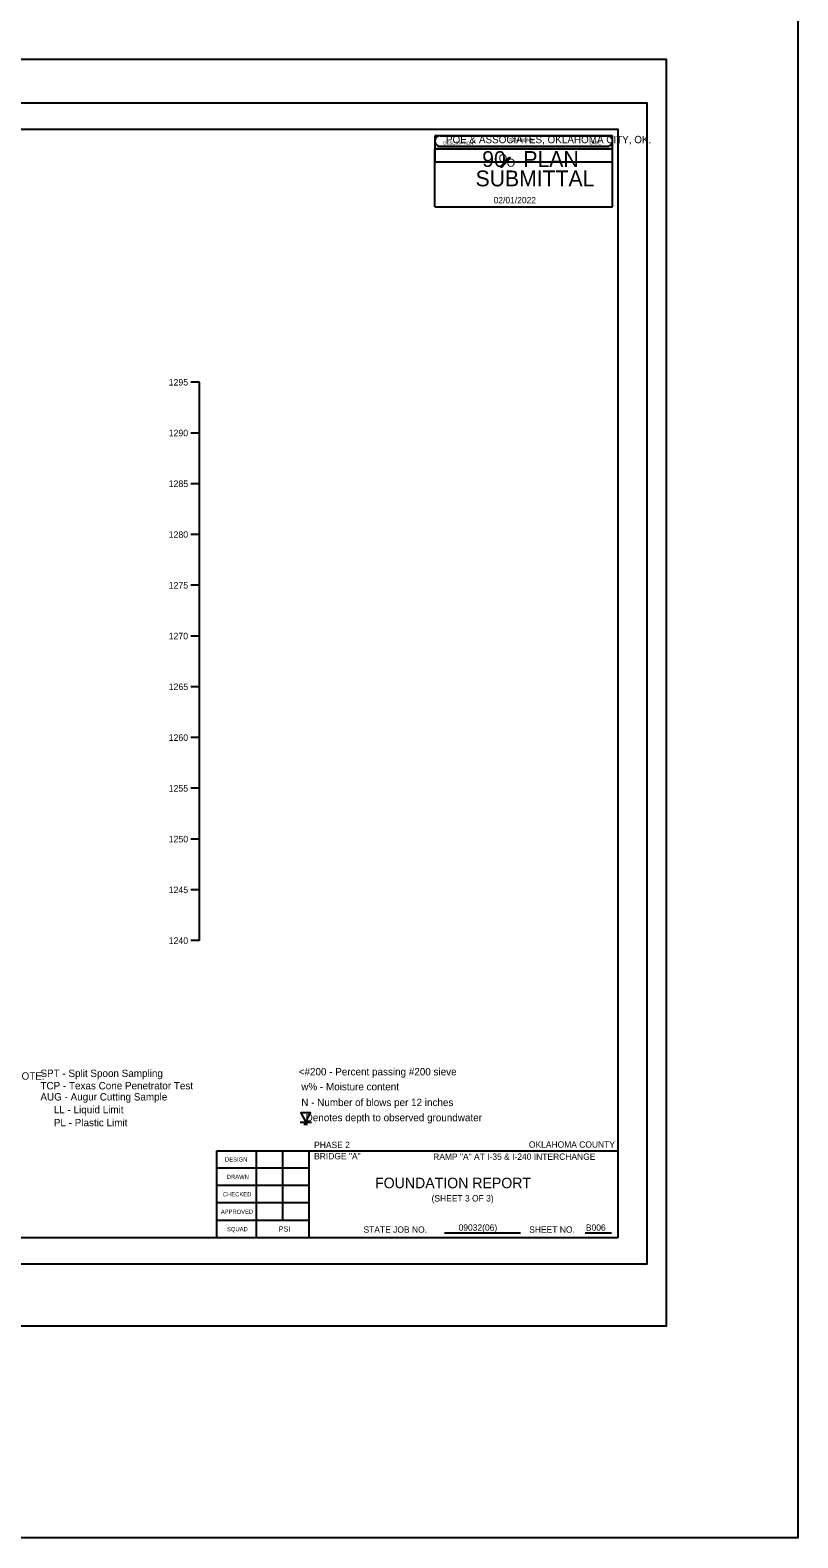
# Model space of a CAD drawing. Extents: x 2150161.5 to 2150203.1, y 143779.5 to 143868.5.
# Drawn here: x 2150188.52 to 2150203.07, y 143779.54 to 143808.09 of the extents above; entities that cross this region are included whole.
import ezdxf

# ---------------------------------------------------------------- set-up
doc = ezdxf.new("R2010")
doc.units = 0
for name, color, linetype in [('Default', 7, 'Continuous'), ('S', 7, 'Continuous'), ('SHT_Plot_Shape_Full', 7, 'Continuous'), ('SHT_Plot_Shape_Half', 7, 'Continuous'), ('SHT_Sheet_Border', 7, 'Continuous'), ('SHT_Stamp_90_Submit', 7, 'Continuous'), ('SHT_Stamp_Rev_Block', 7, 'Continuous'), ('SHT_Standard_Sheet_Lines', 7, 'Continuous'), ('SHT_Standard_Sheet_Txt', 7, 'Continuous'), ('T', 7, 'Continuous'), ('T-Title', 7, 'Continuous'), ('Text', 7, 'Continuous')]:
    doc.layers.add(name, color=color, linetype=linetype)

# ---------------------------------------------------------------- blocks, each defined once
blk = doc.blocks.new('DGRFC_WTLEV1')
at = {"layer": 'Default'}
for points in [[(-0.0127, 0), (0.0127, 0)], [(0, 0), (0.0106, 0.0212), (-0.0106, 0.0212), (0, 0)], [(-0.0042, -0.0042), (0.0042, -0.0042)]]:
    blk.add_lwpolyline(points, dxfattribs=at)

msp = doc.modelspace()

# ---------------------------------------------------------------- linework, layer by layer
at = {"layer": 'Default'}
msp.add_line((2150191.733, 143790.848), (2150191.733, 143801.425), dxfattribs=at)
for points in [[(2150191.733, 143801.425), (2150191.567, 143801.425)], [(2150191.733, 143801.425), (2150191.567, 143801.425)], [(2150191.733, 143800.463), (2150191.567, 143800.463)], [(2150191.733, 143799.502), (2150191.567, 143799.502)], [(2150191.733, 143798.54), (2150191.567, 143798.54)], [(2150191.733, 143797.579), (2150191.567, 143797.579)], [(2150191.733, 143796.617), (2150191.567, 143796.617)], [(2150191.733, 143795.656), (2150191.567, 143795.656)], [(2150191.733, 143794.694), (2150191.567, 143794.694)], [(2150191.733, 143793.733), (2150191.567, 143793.733)], [(2150191.733, 143792.771), (2150191.567, 143792.771)], [(2150191.733, 143791.81), (2150191.567, 143791.81)], [(2150191.733, 143791.81), (2150191.567, 143791.81)], [(2150191.733, 143790.848), (2150191.567, 143790.848)], [(2150191.733, 143790.848), (2150191.567, 143790.848)]]:
    msp.add_lwpolyline(points, dxfattribs=at)
at = {"layer": 'S'}
msp.add_lwpolyline([(2150161.53, 143868.477), (2150203.071, 143868.477), (2150203.071, 143779.536), (2150161.53, 143779.536)], close=True, dxfattribs=at)
at = {"layer": 'SHT_Plot_Shape_Full'}
msp.add_lwpolyline([(2150164.575, 143807.544), (2150200.575, 143807.544), (2150200.575, 143783.544), (2150164.575, 143783.544)], close=True, dxfattribs=at)
at = {"layer": 'SHT_Plot_Shape_Half'}
msp.add_lwpolyline([(2150166.212, 143806.719), (2150200.212, 143806.719), (2150200.212, 143784.719), (2150166.212, 143784.719)], close=True, dxfattribs=at)
at = {"layer": 'SHT_Sheet_Border'}
for p, q in [((2150192.062, 143785.219), (2150192.062, 143786.869)), ((2150192.062, 143786.869), (2150199.662, 143786.869)), ((2150193.812, 143785.219), (2150193.812, 143786.87))]:
    msp.add_line(p, q, dxfattribs=at)
msp.add_lwpolyline([(2150199.662, 143785.219), (2150168.162, 143785.219), (2150168.162, 143806.219), (2150199.662, 143806.219)], close=True, dxfattribs=at)
at = {"layer": 'SHT_Stamp_90_Submit'}
for p, q in [((2150196.293, 143806.095), (2150199.459, 143806.095)), ((2150196.193, 143805.845), (2150199.559, 143805.845)), ((2150196.193, 143804.746), (2150196.193, 143805.845)), ((2150196.293, 143805.895), (2150199.459, 143805.895)), ((2150199.559, 143804.746), (2150199.559, 143805.845)), ((2150197.437, 143805.506), (2150197.592, 143805.679)), ((2150197.437, 143805.506), (2150197.467, 143805.506)), ((2150197.454, 143805.506), (2150197.61, 143805.679)), ((2150197.459, 143805.506), (2150197.615, 143805.679)), ((2150197.467, 143805.506), (2150197.623, 143805.679)), ((2150197.592, 143805.679), (2150197.623, 143805.679)), ((2150196.193, 143804.746), (2150199.559, 143804.746))]:
    msp.add_line(p, q, dxfattribs=at)
for centre, start, end in [((2150196.294, 143805.995), 89.9952, 270), ((2150199.46, 143805.995), 270, 90.0048)]:
    msp.add_arc(centre, 0.1, start, end, dxfattribs=at)
at = {"layer": 'SHT_Stamp_Rev_Block'}
for p, q in [((2150196.194, 143806.095), (2150196.194, 143805.595)), ((2150199.559, 143806.095), (2150196.194, 143806.095)), ((2150199.559, 143805.595), (2150199.559, 143806.095)), ((2150199.559, 143805.845), (2150196.194, 143805.845)), ((2150199.559, 143805.595), (2150196.194, 143805.595))]:
    msp.add_line(p, q, dxfattribs=at)
at = {"layer": 'SHT_Standard_Sheet_Lines'}
for p, q in [((2150192.812, 143785.219), (2150192.812, 143786.87)), ((2150193.312, 143785.549), (2150193.312, 143786.87)), ((2150196.373, 143785.315), (2150197.813, 143785.315)), ((2150199.038, 143785.315), (2150199.54, 143785.315))]:
    msp.add_line(p, q, dxfattribs=at)
for points in [[(2150193.812, 143786.539), (2150192.062, 143786.539)], [(2150193.812, 143786.209), (2150192.062, 143786.209)], [(2150193.812, 143785.879), (2150192.062, 143785.879)], [(2150193.812, 143785.549), (2150192.062, 143785.549)]]:
    msp.add_lwpolyline(points, dxfattribs=at)

# ---------------------------------------------------------------- block references
at = {"layer": 'Default', "xscale": 8.503919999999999, "yscale": 8.503919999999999}
msp.add_blockref('DGRFC_WTLEV1', (2150193.745, 143787.409), dxfattribs=at)

# ---------------------------------------------------------------- texts
at = {"layer": 'Default'}
for s, p in [('1295', (2150191.148, 143801.363)), ('1290', (2150191.148, 143800.401)), ('1285', (2150191.148, 143799.44)), ('1280', (2150191.148, 143798.478)), ('1275', (2150191.148, 143797.517)), ('1270', (2150191.148, 143796.555)), ('1265', (2150191.148, 143795.594)), ('1260', (2150191.148, 143794.632)), ('1255', (2150191.148, 143793.671)), ('1250', (2150191.148, 143792.709)), ('1245', (2150191.148, 143791.748)), ('1240', (2150191.148, 143790.786))]:
    msp.add_text(s, height=0.124, rotation=0.0001, dxfattribs=at).set_placement(p)
at = {"layer": 'SHT_Stamp_90_Submit'}
for s, height, p in [('POE & ASSOCIATES, OKLAHOMA CITY, OK.', 0.14, (2150196.403, 143805.952)), ('90   PLAN', 0.3, (2150197.089, 143805.503)), ('O', 0.153, (2150197.402, 143805.591)), ('O', 0.153, (2150197.554, 143805.507)), ('SUBMITTAL', 0.3, (2150196.964, 143805.136)), ('02/01/2022', 0.12, (2150197.306, 143804.814))]:
    msp.add_text(s, height=height, dxfattribs=at).set_placement(p)
at = {"layer": 'SHT_Stamp_Rev_Block'}
for s, height, p in [('DESCRIPTION', 0.05999, (2150196.353, 143805.923)), ('REVISIONS', 0.06, (2150197.602, 143805.982)), ('DATE', 0.06, (2150199.123, 143805.927))]:
    msp.add_text(s, height=height, dxfattribs=at).set_placement(p)
at = {"layer": 'SHT_Standard_Sheet_Txt'}
for s, height, p in [('DESIGN', 0.08, (2150192.215, 143786.664)), ('DRAWN', 0.08, (2150192.25, 143786.334)), ('CHECKED', 0.08, (2150192.175, 143786.004)), ('APPROVED', 0.08, (2150192.136, 143785.673)), ('SQUAD', 0.08, (2150192.254, 143785.343)), ('STATE JOB NO.', 0.12, (2150194.84, 143785.315)), ('SHEET NO. ', 0.12, (2150197.98, 143785.315))]:
    msp.add_text(s, height=height, dxfattribs=at).set_placement(p)
at = {"layer": 'T'}
for s, height, p in [('PHASE 2', 0.12, (2150193.904, 143786.918)), ('OKLAHOMA COUNTY', 0.12, (2150197.974, 143786.926)), ('BRIDGE "A"', 0.12, (2150193.904, 143786.706)), ('RAMP "A" AT I-35 & I-240 INTERCHANGE', 0.12, (2150196.16, 143786.696)), ('(SHEET 3 OF 3)', 0.12, (2150196.13, 143785.907)), ('PSI', 0.1, (2150193.232, 143785.337)), ('09032(06)', 0.12, (2150196.642, 143785.353)), ('B006', 0.12, (2150199.054, 143785.353))]:
    msp.add_text(s, height=height, dxfattribs=at).set_placement(p)
at = {"layer": 'T-Title'}
msp.add_text('FOUNDATION REPORT', height=0.2, dxfattribs=at).set_placement((2150195.059, 143786.158))
at = {"layer": 'Text'}
for s, p in [('    SPT - Split Spoon Sampling', (2150188.51, 143788.265)), (' <#200 - Percent passing #200 sieve', (2150193.56, 143788.295)), ('NOTE:', (2150188.226, 143788.214)), ('    TCP - Texas Cone Penetrator Test', (2150188.51, 143788.03)), ('w% - Moisture content', (2150193.661, 143788.013)), ('    AUG - Augur Cutting Sample', (2150188.51, 143787.82)), ('N - Number of blows per 12 inches', (2150193.661, 143787.714)), (' LL - Liquid Limit', (2150188.92, 143787.578)), ('    Denotes depth to observed groundwater', (2150193.536, 143787.427)), (' PL - Plastic Limit', (2150188.92, 143787.331))]:
    msp.add_text(s, height=0.14, dxfattribs=at).set_placement(p)

doc.saveas('drawing.dxf')
